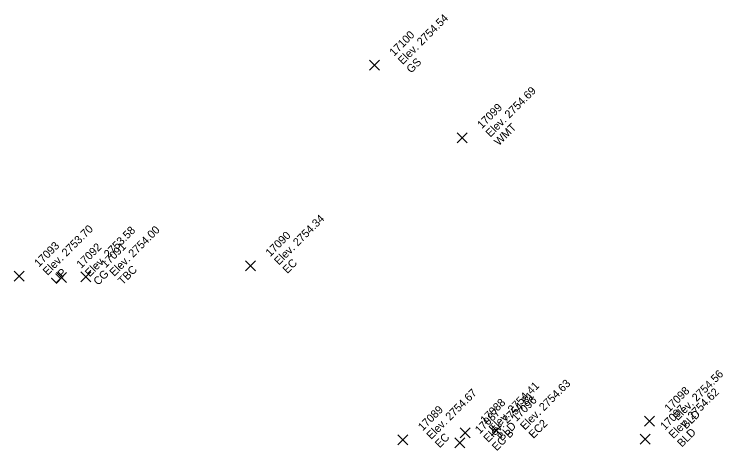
# Model space of a CAD drawing. Extents: x 2493999 to 2503109, y 700767 to 706646.
# Drawn here: x 2502327.61 to 2502348.85, y 704154.86 to 704167.95 of the extents above; entities that cross this region are included whole.
import ezdxf

# ---------------------------------------------------------------- set-up
doc = ezdxf.new("R2010")
doc.units = 0
doc.layers.add('ALG_CL_BLUE_Horiz', color=7, linetype='Continuous')
doc.layers.add('DES_SURFACE_Existing-Ground', color=7, linetype='Continuous')

msp = doc.modelspace()

# ---------------------------------------------------------------- linework, layer by layer
at = {"layer": 'ALG_CL_BLUE_Horiz'}
for points in [[(2502338.404, 704166.423), (2502338.254, 704166.573), (2502338.404, 704166.423), (2502338.254, 704166.273), (2502338.404, 704166.423), (2502338.554, 704166.273), (2502338.404, 704166.423), (2502338.554, 704166.573)], [(2502341.033, 704164.247), (2502340.883, 704164.397), (2502341.033, 704164.247), (2502340.883, 704164.097), (2502341.033, 704164.247), (2502341.183, 704164.097), (2502341.033, 704164.247), (2502341.183, 704164.397)], [(2502334.692, 704160.413), (2502334.542, 704160.563), (2502334.692, 704160.413), (2502334.542, 704160.263), (2502334.692, 704160.413), (2502334.842, 704160.263), (2502334.692, 704160.413), (2502334.842, 704160.563)], [(2502327.759, 704160.102), (2502327.609, 704160.252), (2502327.759, 704160.102), (2502327.609, 704159.952), (2502327.759, 704160.102), (2502327.909, 704159.952), (2502327.759, 704160.102), (2502327.909, 704160.252)], [(2502329.023, 704160.061), (2502328.873, 704160.211), (2502329.023, 704160.061), (2502328.873, 704159.911), (2502329.023, 704160.061), (2502329.173, 704159.911), (2502329.023, 704160.061), (2502329.173, 704160.211)], [(2502329.757, 704160.076), (2502329.607, 704160.226), (2502329.757, 704160.076), (2502329.607, 704159.926), (2502329.757, 704160.076), (2502329.907, 704159.926), (2502329.757, 704160.076), (2502329.907, 704160.226)], [(2502346.647, 704155.755), (2502346.497, 704155.905), (2502346.647, 704155.755), (2502346.497, 704155.605), (2502346.647, 704155.755), (2502346.797, 704155.605), (2502346.647, 704155.755), (2502346.797, 704155.905)], [(2502341.128, 704155.402), (2502340.978, 704155.552), (2502341.128, 704155.402), (2502340.978, 704155.252), (2502341.128, 704155.402), (2502341.278, 704155.252), (2502341.128, 704155.402), (2502341.278, 704155.552)], [(2502342.067, 704155.473), (2502341.917, 704155.623), (2502342.067, 704155.473), (2502341.917, 704155.323), (2502342.067, 704155.473), (2502342.217, 704155.323), (2502342.067, 704155.473), (2502342.217, 704155.623)], [(2502339.26, 704155.188), (2502339.11, 704155.338), (2502339.26, 704155.188), (2502339.11, 704155.038), (2502339.26, 704155.188), (2502339.41, 704155.038), (2502339.26, 704155.188), (2502339.41, 704155.338)], [(2502346.52, 704155.212), (2502346.37, 704155.362), (2502346.52, 704155.212), (2502346.37, 704155.062), (2502346.52, 704155.212), (2502346.67, 704155.062), (2502346.52, 704155.212), (2502346.67, 704155.362)], [(2502340.967, 704155.099), (2502340.817, 704155.249), (2502340.967, 704155.099), (2502340.817, 704154.949), (2502340.967, 704155.099), (2502341.117, 704154.949), (2502340.967, 704155.099), (2502341.117, 704155.249)]]:
    msp.add_lwpolyline(points, dxfattribs=at)

# ---------------------------------------------------------------- texts
at = {"layer": 'DES_SURFACE_Existing-Ground'}
for s, p in [('Elev. 2754.54', (2502339.253, 704166.423)), ('17100', (2502338.998, 704166.678)), ('GS', (2502339.507, 704166.168)), ('Elev. 2754.69', (2502341.882, 704164.247)), ('17099', (2502341.627, 704164.502)), ('WMT', (2502342.136, 704163.992)), ('Elev. 2754.34', (2502335.541, 704160.413)), ('Elev. 2753.70', (2502328.608, 704160.102)), ('Elev. 2753.58', (2502329.872, 704160.061)), ('Elev. 2754.00', (2502330.606, 704160.076)), ('17090', (2502335.286, 704160.668)), ('17093', (2502328.353, 704160.357)), ('17092', (2502329.617, 704160.316)), ('17091', (2502330.351, 704160.331)), ('EC', (2502335.795, 704160.158)), ('TBC', (2502330.86, 704159.821)), ('LIP', (2502328.862, 704159.847)), ('CG', (2502330.126, 704159.806)), ('Elev. 2754.56', (2502347.496, 704155.755)), ('Elev. 2754.63', (2502342.916, 704155.473)), ('Elev. 2754.41', (2502341.977, 704155.402)), ('17098', (2502347.241, 704156.01)), ('Elev. 2754.67', (2502340.109, 704155.188)), ('Elev. 2754.81', (2502341.816, 704155.099)), ('Elev. 2754.62', (2502347.369, 704155.212)), ('17088', (2502341.722, 704155.657)), ('17096', (2502342.661, 704155.728)), ('17089', (2502339.854, 704155.443)), ('17087', (2502341.561, 704155.354)), ('17097', (2502347.114, 704155.467)), ('BLD', (2502347.75, 704155.5)), ('BLD', (2502342.231, 704155.147)), ('EC2', (2502343.17, 704155.218)), ('EC B', (2502342.07, 704154.844)), ('BLD', (2502347.623, 704154.957)), ('EC', (2502340.363, 704154.933))]:
    msp.add_text(s, height=0.24, rotation=45, dxfattribs=at).set_placement(p)

doc.saveas('drawing.dxf')
